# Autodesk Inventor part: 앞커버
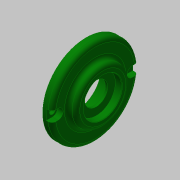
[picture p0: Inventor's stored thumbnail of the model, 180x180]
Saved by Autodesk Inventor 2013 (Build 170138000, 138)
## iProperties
Created: 2019-06
Part Number: 앞커버
Material: 알루미늄 6061
Document SubType Name: Modeling
Designer: mduedu
Density: 1 g/cm^3
Author: mduedu
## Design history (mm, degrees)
sketch "스케치1"
  geometry: L1 (0, 0)-(7, 0); L2 (7, 0)-(7, 25); L3 (7, 25)-(0, 25); L4 (0, 25)-(0, 0); L5 (7, 0)-(14, 0); L6 (14, 0)-(14, 34); L7 (14, 34)-(7, 34); L8 (7, 34)-(7, 0); L9 (14, 0)-(20, 0); L10 (20, 0)-(20, 21); L11 (20, 21)-(14, 21); L12 (14, 21)-(14, 0)
  constraints: 24 end point, 6 parallel, 3 horizontal, 3 perpendicular
  dimensions: "d0" = 20 distance between parallel lines of L10 L4; "d2" = 7 distance of L2.end L3.end; "d3" = 7 distance of L6.end L7.end; "d4" = 50 diameter of L3 L1; "d5" = 68 diameter of L7 L5; "d6" = 42 diameter of L11 L9
revolve "회전1" sketch "스케치1" stored, may be unused: angle "d7" = 90 deg
sketch "스케치2"
  geometry: L1 (0, -25)-(0, 25) reference; L2 (0, 25)-(7, 25) reference; L3 (7, 25)-(7, 34) reference; L4 (7, 34)-(14, 34) reference; L5 (14, 34)-(14, 21) reference; L6 (14, 21)-(20, 21) reference; L7 (20, 21)-(20, -21) reference; L8 (20, -21)-(14, -21) reference; L9 (14, -21)-(14, -34) reference; L10 (14, -34)-(7, -34) reference; L11 (7, -34)-(7, -25) reference; L12 (7, -25)-(0, -25) reference; L13 (10, 0)-(10, 17.5); L14 (10, 17.5)-(0, 17.5); L15 (0, 17.5)-(0, 0); L16 (13, 0)-(13, 15); L17 (13, 15)-(10, 15); L18 (10, 15)-(10, 0); L19 (14.8, 0)-(14.8, 9); L20 (14.8, 9)-(13, 9); L21 (13, 9)-(13, 0); L22 (20, 0)-(20, 15); L23 (20, 15)-(14.8, 15); L24 (14.8, 15)-(14.8, 0)
  constraints: 24 end point, 4 horizontal, 4 horizontal alignment, 4 parallel, 4 vertical, 1 point on line, 8 other
  dimensions: "d8" = 35 dimension on L14; "d10" = 30 dimension on L17; "d11" = 18 dimension on L20; "d12" = 30 dimension on L23; "d13" = 10 distance of L13.end L14.end; "d14" = 3 distance of L16.end L17.end; "d15" = 5.2 distance of L22.end L23.end
revolve "회전2" sketch "스케치2" stored, may be unused: angle "d16" = 90 deg
chamfer "모따기1" distance "d18" = 0.5; stored, may be unused: second distance "d19" = 2, angle "d20" = 30 deg
fillet "모깎기2" dims "d21" = 0.3
fillet "모깎기3" dims "d22" = 3
chamfer "모따기2" distance "d23" = 1; stored, may be unused: second distance "d24" = 2, angle "d25" = 30 deg
fillet "모깎기4" dims "d26" = 3
sketch "스케치3" dims "d27" = 58
  geometry: L1 (-4, 29)-(-4, 33.764); L2 (4, 33.764)-(4, 29); A1 r 4 centre (0, 29) between (-4, 29) and (4, 29); A2 r 34 centre (0, 0) between (4, 33.764) and (-4, 33.764); A3 r 34 centre (0, 0) between (4, 33.764) and (-4, 33.764) reference; 3 further points
  constraints: 6 point on circle, 4 end point, 3 coincident, 2 centre point, 2 tangent, 2 vertical, 2 vertical alignment, 1 concentric, 2 other
  dimensions: "d28" = 8 diameter of A1
extrude "돌출1" cut sketch "스케치3" distance "d29" = 4.4; taper "d30" = 0 deg
sketch "스케치4"
  geometry: A1 r 4 centre (0, 29) between (-4, 29) and (4, 29) reference; 2 further points
  constraints: 1 coincident
hole "구멍1" sketch "스케치4" at (0, 29) diameter "d34" = 4.5; stored, may be unused: countersink angle "d38" = 90 deg, drill point angle "d40" = 118 deg; dims "d35" = 6, "d36" = 4, "d37" = 2, "d39" = 8
node "솔리드1"
pattern_circular "원형 패턴1" dims angle "d32" = 360 deg
pattern_circular "원형 패턴2" dims angle "d42" = 360 deg
node "절단 모서리 투영1"
